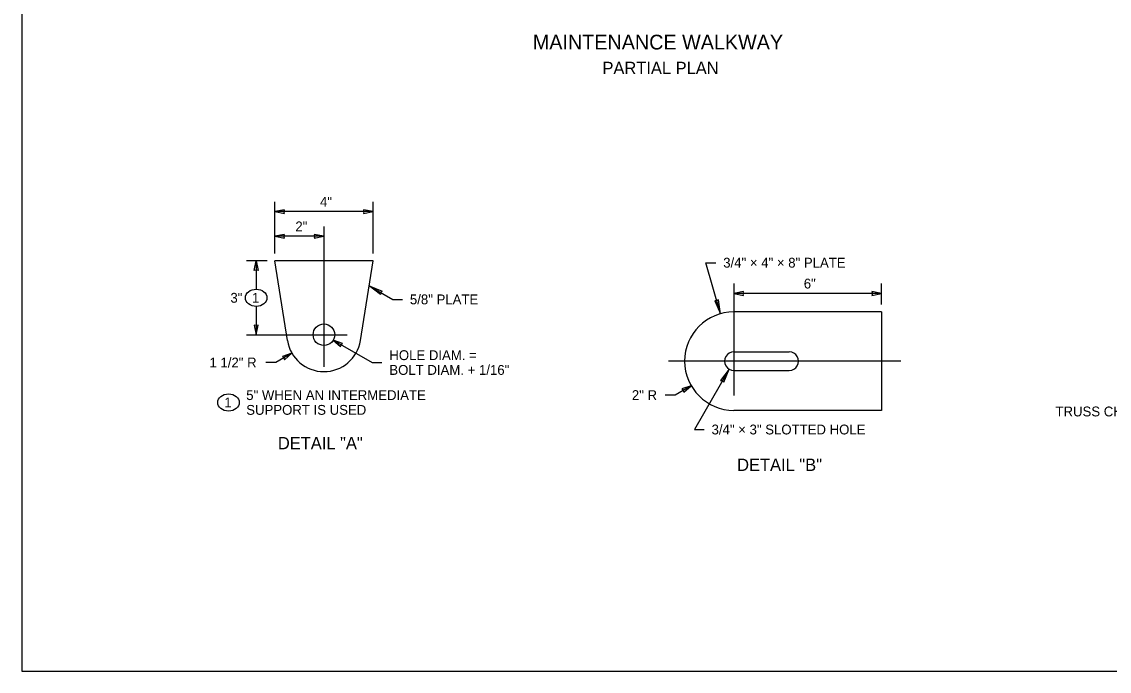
# Model space of a CAD drawing. Extents: x 99862 to 103151, y 100000 to 105076.
# Drawn here: x 99862 to 101629, y 103000 to 104055 of the extents above; entities that cross this region are included whole.
import ezdxf

# ---------------------------------------------------------------- set-up
doc = ezdxf.new("R2010")
doc.units = 0
for name, color, linetype in [('Level 1', 7, 'Continuous'), ('Level 15', 7, 'Continuous'), ('Level 2', 7, 'Continuous'), ('Level 20', 7, 'Continuous'), ('Level 6', 7, 'Continuous'), ('Level 60', 7, 'Continuous')]:
    doc.layers.add(name, color=color, linetype=linetype)

msp = doc.modelspace()

# ---------------------------------------------------------------- linework, layer by layer
at = {"layer": 'Level 1'}
msp.add_lwpolyline([(99862, 102999.5), (103151, 102999.5), (103151, 105075.5), (99862, 105075.5)], close=True, dxfattribs=at)
at = {"layer": 'Level 15'}
for p, q in [((100272.9, 103678.3), (100272.9, 103762.3)), ((100432.9, 103678.3), (100432.9, 103762.3)), ((100432.9, 103746.3), (100272.9, 103746.3)), ((100352.9, 103722.3), (100352.9, 103494)), ((100352.9, 103706.3), (100272.9, 103706.3)), ((100260.9, 103666.3), (100226.9, 103666.3)), ((100242.9, 103666.3), (100242.9, 103620.3)), ((100973.6, 103663.4), (100989.6, 103663.4)), ((100997.1, 103580.3), (100973.6, 103663.4)), ((100426.4, 103625.8), (100464.6, 103603.7)), ((101018.9, 103629.4), (101018.9, 103447.4)), ((101258.9, 103595.4), (101258.9, 103629.4)), ((100464.6, 103603.7), (100480.6, 103603.7)), ((101258.9, 103613.4), (101018.9, 103613.4)), ((100242.9, 103592.3), (100242.9, 103546.3)), ((100226.9, 103546.3), (100390.5, 103546.3)), ((100368, 103537.5), (100431.2, 103501.1)), ((100300.9, 103516.3), (100274.6, 103501.1)), ((100274.6, 103501.1), (100258.6, 103501.1)), ((100431.2, 103501.1), (100447.2, 103501.1)), ((101290, 103503.4), (100912.6, 103503.4)), ((101011.4, 103490.4), (100954.7, 103392.2)), ((100949.6, 103463.4), (100923.3, 103448.2)), ((100923.3, 103448.2), (100907.3, 103448.2)), ((100954.7, 103392.2), (100970.7, 103392.2))]:
    msp.add_line(p, q, dxfattribs=at)
for points in [[(100272.9, 103746.3), (100288.6, 103743.2), (100287.9, 103746.3), (100288.6, 103749.4)], [(100432.9, 103746.3), (100417.1, 103749.4), (100417.9, 103746.3), (100417.1, 103743.2)], [(100272.9, 103706.3), (100288.6, 103703.2), (100287.9, 103706.3), (100288.6, 103709.4)], [(100352.9, 103706.3), (100337.1, 103709.4), (100337.9, 103706.3), (100337.1, 103703.2)], [(100242.9, 103666.3), (100245.9, 103650.5), (100242.9, 103651.3), (100239.8, 103650.5)], [(100426.4, 103625.8), (100447.6, 103616.9), (100445.2, 103614.9), (100444.7, 103611.8)], [(100997.1, 103580.3), (100993.7, 103603.1), (100991.1, 103601.3), (100988, 103601.5)], [(101018.9, 103613.4), (101034.6, 103610.3), (101033.9, 103613.4), (101034.6, 103616.4)], [(101258.9, 103613.4), (101243.2, 103616.4), (101243.9, 103613.4), (101243.2, 103610.3)], [(100242.9, 103546.3), (100245.9, 103562), (100242.9, 103561.3), (100239.8, 103562)], [(100368, 103537.5), (100380.1, 103527), (100381, 103530), (100383.2, 103532.3)], [(100300.9, 103516.3), (100285.7, 103511.1), (100287.9, 103508.8), (100288.8, 103505.7)], [(101011.4, 103490.4), (100997.4, 103472.1), (101000.5, 103471.5), (101002.6, 103469.1)], [(100949.6, 103463.4), (100934.4, 103458.2), (100936.6, 103455.9), (100937.5, 103452.8)]]:
    msp.add_lwpolyline(points, close=True, dxfattribs=at)
at = {"layer": 'Level 2'}
for p, q in [((101258.9, 103583.4), (101018.9, 103583.4)), ((101258.9, 103583.4), (101258.9, 103423.4)), ((101018.9, 103518.4), (101108.9, 103518.4)), ((101018.9, 103488.4), (101108.9, 103488.4)), ((101258.9, 103423.4), (101018.9, 103423.4))]:
    msp.add_line(p, q, dxfattribs=at)
for centre, radius, start, end in [((101018.9, 103503.4), 80, 90, 270), ((101018.9, 103503.4), 15, 89.9978, 270), ((101108.9, 103503.4), 15, 270, 90.0022)]:
    msp.add_arc(centre, radius, start, end, dxfattribs=at)
at = {"layer": 'Level 20'}
for centre in [(100242.9, 103606.3), (100197.9, 103436.2)]:
    msp.add_ellipse(centre, major_axis=(-17.5, 0), ratio=0.8, dxfattribs=at)
at = {"layer": 'Level 6'}
for p, q in [((100352.9, 103666.3), (100272.9, 103666.3)), ((100293.6, 103536.8), (100272.9, 103666.3)), ((100432.9, 103666.3), (100352.9, 103666.3)), ((100412.1, 103536.8), (100432.9, 103666.3))]:
    msp.add_line(p, q, dxfattribs=at)
msp.add_circle((100352.9, 103546.3), 17.5, dxfattribs=at)
for start, end in [(189.1049, 270.0022), (270.0022, 350.8942)]:
    msp.add_arc((100352.9, 103546.3), 60, start, end, dxfattribs=at)
at = {"layer": 'Level 60'}
msp.add_line((99862, 102999.5), (99862, 102999.5), dxfattribs=at)

# ---------------------------------------------------------------- texts
at = {"layer": 'Level 20'}
for s, height, p in [('MAINTENANCE WALKWAY', 24, (100692.3, 104009.8)), ('PARTIAL PLAN', 20, (100805.4, 103969.8)), ('4"', 16, (100346.5, 103754.3)), ('2"', 16, (100306.5, 103714.3)), ('3/4" × 4" × 8" PLATE', 16, (101001.6, 103655.4)), ('6"', 16, (101132.5, 103621.4)), ('3"', 16, (100201, 103598.3)), ('1', 16, (100236, 103598.3)), ('5/8" PLATE', 16, (100492.6, 103595.7)), ('HOLE DIAM. =', 16, (100459.2, 103505.1)), ('1 1/2" R', 16, (100167, 103493.1)), ('BOLT DIAM. + 1/16"', 16, (100459.2, 103481.1)), ('1', 16, (100191, 103428.2)), ('5" WHEN AN INTERMEDIATE', 16, (100226.7, 103440.2)), ('2" R', 16, (100853.2, 103440.2)), ('SUPPORT IS USED', 16, (100226.7, 103416.2)), ('TRUSS CHORD', 16, (101541.4, 103413.6)), ('3/4" × 3" SLOTTED HOLE', 16, (100982.7, 103384.3)), ('DETAIL "A"', 20, (100278.1, 103360.2)), ('DETAIL "B"', 20, (101024.2, 103325))]:
    msp.add_text(s, height=height, dxfattribs=at).set_placement(p)

doc.saveas('drawing.dxf')
